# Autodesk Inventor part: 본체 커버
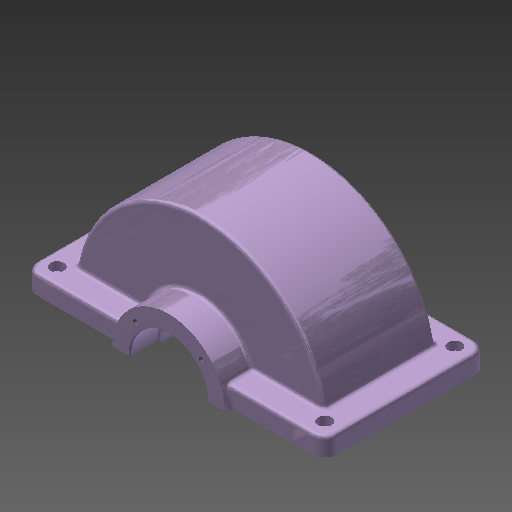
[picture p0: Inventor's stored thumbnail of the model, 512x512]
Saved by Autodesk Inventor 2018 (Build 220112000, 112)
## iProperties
Created: 2023-06
Part Number: 본체 커버
Material: 알루미늄 6061
Document SubType Name: Modeling
Designer: mdu-01
Density: 1 g/cm^3
Appearance: 알루미늄 - 평지(1)
Author: mdu-01
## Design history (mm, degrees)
sketch "스케치1"
  geometry: L1 (0, 70)-(0, -70); L2 (0, 70)-(45, 70); L3 (45, 70)-(45, 45); L4 (45, 45)-(100, 45); L5 (0, 0)-(100, 0); L6 (0, -70)-(45, -70); L7 (45, -70)-(45, -45); L8 (45, -45)-(100, -45); L9 (100, 45)-(100, -45); 1 further point
  constraints: 18 end point, 3 perpendicular, 3 symmetric about line, 2 midpoint, 2 parallel, 1 coincident, 1 vertical
  dimensions: "d0" = 140 distance of L1.start L1.end; "d1" = 90 diameter of L3 L1; "d2" = 90 distance between parallel lines of L8 L4; "d3" = 200 diameter of L9 L1
revolve "회전1" sketch "스케치1" stored, may be unused: angle "d4" = 180 deg
sketch "스케치2"
  geometry: L1 (-10, -110)-(210, -110); L2 (220, -100)-(220, 10); L3 (210, 20)-(-10, 20); L4 (-20, 10)-(-20, -100); L5 (-20, -110)-(220, 20); L6 (220, -110)-(-20, 20); A1 r 10 centre (-10, 10) between (-10, 20) and (-20, 10); A2 r 10 centre (210, 10) between (220, 10) and (210, 20); A3 r 10 centre (210, -100) between (210, -110) and (220, -100); A4 r 10 centre (-10, -100) between (-20, -100) and (-10, -110); 1 further point
  constraints: 12 end point, 8 point on circle, 8 point on line, 8 tangent, 4 centre point, 3 equal radius, 2 midpoint, 2 parallel, 1 horizontal, 1 perpendicular
  dimensions: "d5" = 240 distance of L6.end L5.end; "d6" = 130 distance of L5.end L6.start; "d7" = 10 radius of A1
extrude "돌출1" join sketch "스케치2" distance "d8" = 15; taper "d9" = 0 deg
sketch "스케치3"
  geometry: L1 (0, 70)-(45, 70) reference; L2 (0, -70)-(45, -70) reference; L3 (0, 70)-(0, -70); L4 (31, 70)-(31, 48); L5 (30, 47)-(27.5, 47); L6 (27.5, 47)-(27.5, 32); L7 (27.5, 32)-(87, 32); L8 (0, 0)-(92.097, 0); L9 (31, -70)-(31, -48); L10 (30, -47)-(27.5, -47); L11 (27.5, -47)-(27.5, -32); L12 (27.5, -32)-(87, -32); L13 (87, 32)-(87, -32); L14 (0, 70)-(31, 70); L15 (0, -70)-(31, -70); A1 r 1 centre (30, 48) between (30, 47) and (31, 48); A2 r 1 centre (30, -48) between (31, -48) and (30, -47); 2 further points
  constraints: 26 end point, 5 point on line, 5 symmetric about line, 4 parallel, 4 point on circle, 4 tangent, 3 perpendicular, 2 centre point, 2 collinear, 1 equal radius
  dimensions: "d10" = 1 radius of A1; "d11" = 62 diameter of L4 L3; "d12" = 23 distance between parallel lines of L1 L5; "d13" = 64 distance between parallel lines of L12 L7; "d14" = 55 diameter of L6 L3; "d15" = 87 distance between parallel lines of L13 L3
revolve "회전2" sketch "스케치3" stored, may be unused: angle "d16" = 180 deg
fillet "모깎기1" dims "d17" = 3
fillet "모깎기2" dims "d18" = 3
sketch "스케치4"
  geometry: L1 (-7, -7)-(207, -7); L2 (207, -7)-(207, 97); L3 (207, 97)-(-7, 97); L4 (-7, 97)-(-7, -7); L5 (-7, -7)-(207, 97); L6 (207, -7)-(-7, 97); 1 further point
  constraints: 12 end point, 2 midpoint, 2 parallel, 1 horizontal, 1 perpendicular
  dimensions: "d19" = 214 distance of L3.end L2.end; "d20" = 104 distance of L2.end L1.end
hole "구멍1" sketch "스케치4" at (207, -7), (-7, -7), (207, 97), (-7, 97) diameter "d21" = 6.6; stored, may be unused: countersink angle "d25" = 90 deg, drill point angle "d27" = 118 deg; dims "d22" = 6, "d23" = 11, "d24" = 6.8, "d26" = 8
sketch "스케치5"
  geometry: L1 (-26.163, 26.163)-(26.163, 26.163); L2 (26.163, 26.163)-(26.163, -26.163); L3 (26.163, -26.163)-(-26.163, -26.163); L4 (-26.163, -26.163)-(-26.163, 26.163); A1 r 37 centre (0, 0) between (-26.163, 26.163) and (26.163, -26.163); 1 further point
  constraints: 8 end point, 3 point on circle, 2 parallel, 2 perpendicular, 1 centre point, 1 coincident, 1 horizontal
  dimensions: "d28" = 74 diameter of A1
hole "구멍2" sketch "스케치5" at (-26.163, 26.163), (26.163, 26.163) diameter "d29" = 4.134; stored, may be unused: countersink angle "d33" = 90 deg, drill point angle "d35" = 118 deg; dims "d30" = 10, "d31" = 11, "d32" = 6.8, "d34" = 12
chamfer "모따기1" distance "d36" = 1; stored, may be unused: second distance "d37" = 2, angle "d38" = 45 deg
node "솔리드1"
mirror "대칭1"
